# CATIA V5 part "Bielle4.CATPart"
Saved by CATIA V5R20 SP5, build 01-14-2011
Part number: Bielle3
Bounding box of the stored display mesh (mm): x 0 to 50, y -117.051 to 21.675, z -0.806 to 19.189
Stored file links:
  D:\Dropbox\IAO_2011\MMS_GR1\abruchon\abruchon\Bielle4.CATPart
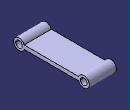
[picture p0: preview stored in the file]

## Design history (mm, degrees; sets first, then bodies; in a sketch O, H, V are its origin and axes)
Body1 (main body)
  Sketch1 on yz-plane, origin (0, 0, 0), H (0, 1, 0), V (0, 0, 1)
    line L1 (-97.6882, 12.6779) -> (2.3118, 12.6779)
    line L2 (2.3118, 5.705) -> (-97.6882, 5.705)
    arc A1 centre (11.6843, 9.1915) radius 10 from (2.3118, 12.6779) to (2.3118, 5.705) cw
    arc A2 centre (-107.0608, 9.1915) radius 10 from (-97.6882, 12.6779) to (-97.6882, 5.705) ccw
    point P7 (-111, 0)
    circle A3 centre (11.6843, 9.1915) radius 6
    circle A4 centre (-107.0608, 9.1915) radius 6
    radius A2 = 10
    length L1 = 100
    length L2 = 100
    horizontal: L1 H, L2 H
    coincidence: A2 P7, P7 H
  Pad1: profile Sketch1, direction (1, 0, 0), length 50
